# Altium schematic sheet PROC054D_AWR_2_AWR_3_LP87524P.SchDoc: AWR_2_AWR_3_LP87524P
size 558 x 431 mm; Date: Not shown in title block; ApprovedBy: Not shown in title block; CheckedBy: Not shown in title block; Author: Not shown in title block; CompanyName: Not shown in title block; DrawnBy: a0271760; Engineer: Not shown in title block; Organization: Not shown in title block; Address1: Not shown in title block; Address2: Not shown in title block; Address3: Not shown in title block; Address4: Not shown in title block; DocumentNumber: 5; Revision: Use project pAWRameter SCH_Rev; SheetNumber: 5; SheetTotal: 19; PageSetup: Record=PageOptions¦CenterHorizontal=True¦CenterVertical=True¦PrintScale=1.00¦XCorrection=1.00¦YCorrection=1.00¦PrintKind=0¦BorderSize=5000000¦LeftOffset=0¦BottomOffset=0¦Orientation=2¦PaperLength=1000¦PaperWidth=1000¦Scale=100¦PaperSource=15¦PrintQuality=600¦MediaType=1¦DitherType=10¦PaperKind=Letter¦PrintScaleMode=1
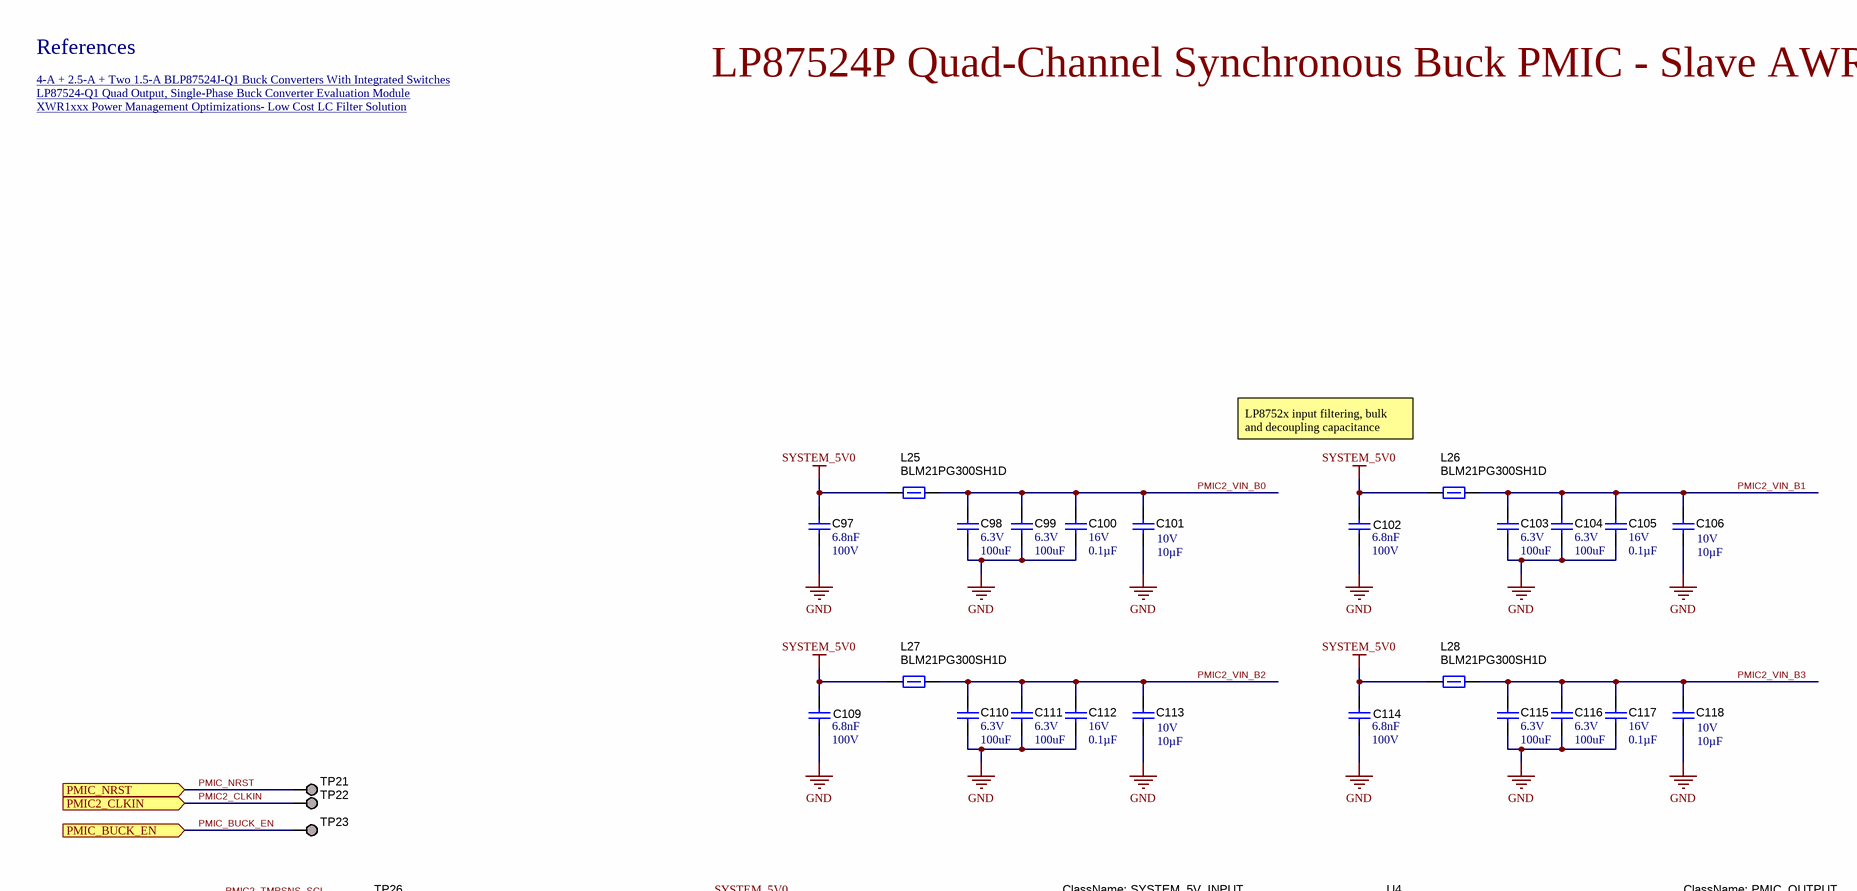
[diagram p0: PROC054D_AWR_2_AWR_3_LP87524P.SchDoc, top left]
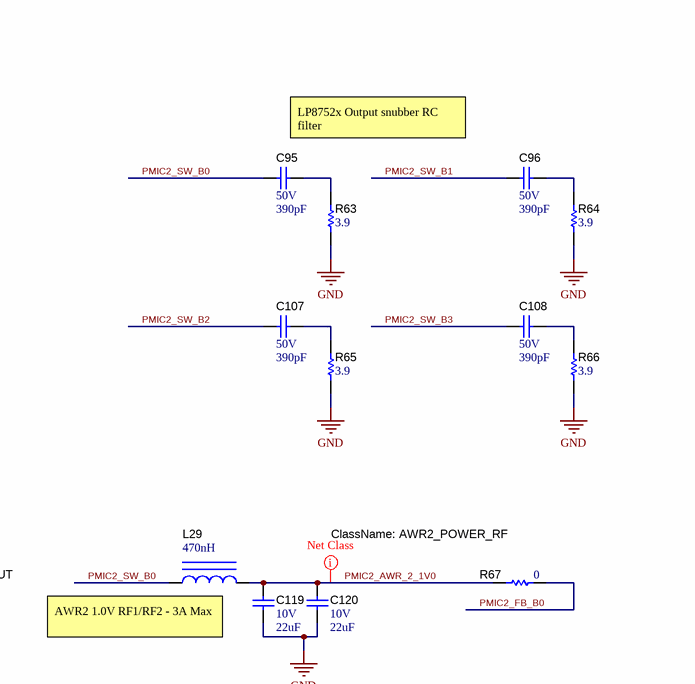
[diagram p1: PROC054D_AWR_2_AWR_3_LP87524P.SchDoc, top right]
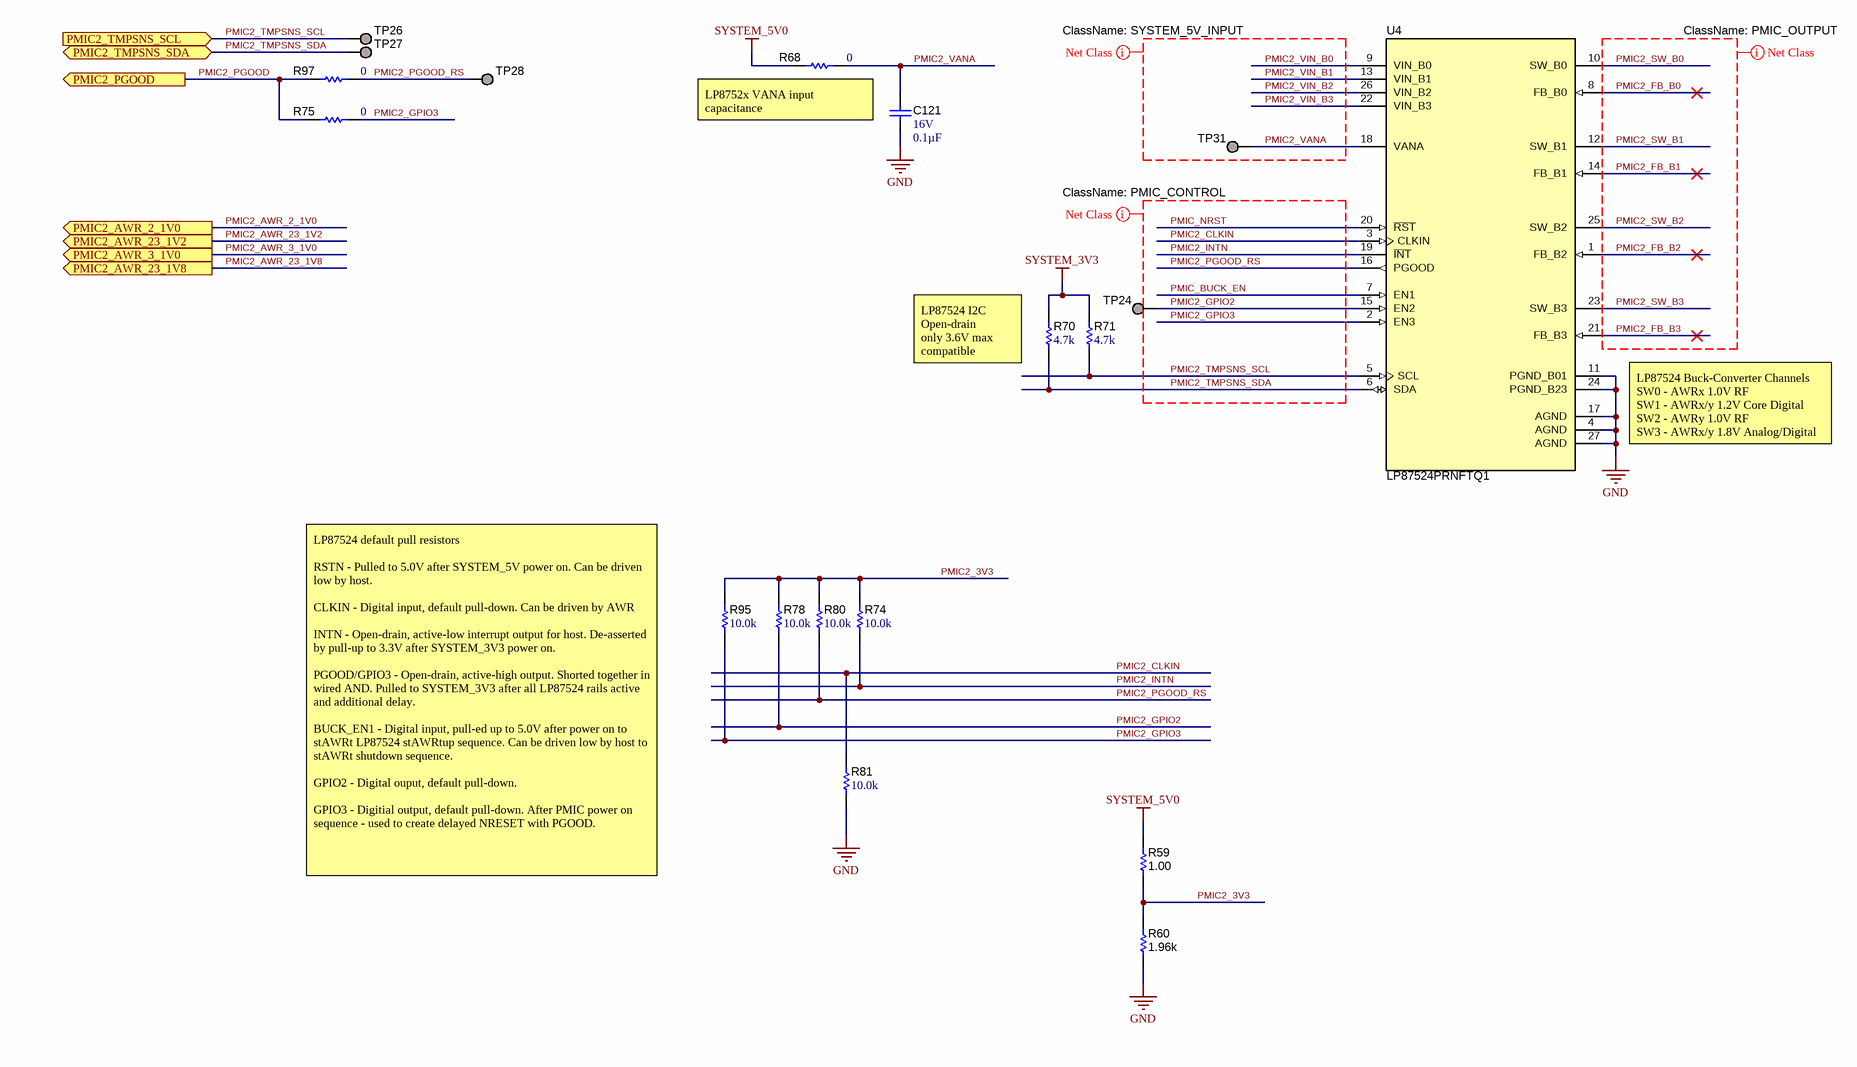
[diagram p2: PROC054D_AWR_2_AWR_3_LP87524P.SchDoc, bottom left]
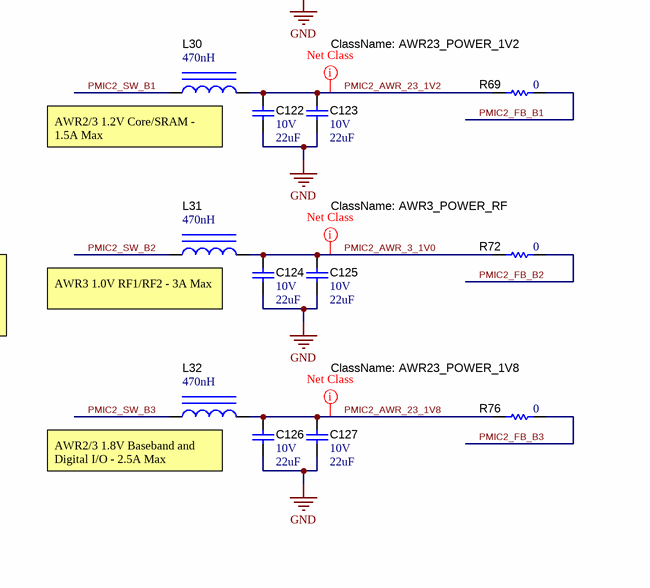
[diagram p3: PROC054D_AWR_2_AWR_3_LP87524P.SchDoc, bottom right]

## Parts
C95  VDC_V: 50V  ValueDisplayed: 390pF  [0402S]  (hidden comment: GCM155R71H391KA37D)
C96  VDC_V: 50V  ValueDisplayed: 390pF  [0402S]  (hidden comment: GCM155R71H391KA37D)
C97  Cap_F: 6.8nF  VDC_V: 100V  [0603S]  (hidden comment: GCM188R72A682KA37D)
C98  VDC_V: 6.3V  ValueDisplayed: 100uF  [0805L]  (hidden comment: GRM21BR60J107M)
C99  VDC_V: 6.3V  ValueDisplayed: 100uF  [0805L]  (hidden comment: GRM21BR60J107M)
C100  VDC_V: 16V  ValueDisplayed: 0.1µF  [0402S]  (hidden comment: GCM155R71C104JA55D)
C101  Cap_F: 10µF  VDC_V: 10V  [0805L]  (hidden comment: GRM21BR71A106KA73L)
C102  Cap_F: 6.8nF  VDC_V: 100V  [0603S]  (hidden comment: GCM188R72A682KA37D)
C103  VDC_V: 6.3V  ValueDisplayed: 100uF  [0805L]  (hidden comment: GRM21BR60J107M)
C104  VDC_V: 6.3V  ValueDisplayed: 100uF  [0805L]  (hidden comment: GRM21BR60J107M)
C105  VDC_V: 16V  ValueDisplayed: 0.1µF  [0402S]  (hidden comment: GCM155R71C104JA55D)
C106  Cap_F: 10µF  VDC_V: 10V  [0805L]  (hidden comment: GRM21BR71A106KA73L)
C107  VDC_V: 50V  ValueDisplayed: 390pF  [0402S]  (hidden comment: GCM155R71H391KA37D)
C108  VDC_V: 50V  ValueDisplayed: 390pF  [0402S]  (hidden comment: GCM155R71H391KA37D)
C109  Cap_F: 6.8nF  VDC_V: 100V  [0603S]  (hidden comment: GCM188R72A682KA37D)
C110  VDC_V: 6.3V  ValueDisplayed: 100uF  [0805L]  (hidden comment: GRM21BR60J107M)
C111  VDC_V: 6.3V  ValueDisplayed: 100uF  [0805L]  (hidden comment: GRM21BR60J107M)
C112  VDC_V: 16V  ValueDisplayed: 0.1µF  [0402S]  (hidden comment: GCM155R71C104JA55D)
C113  Cap_F: 10µF  VDC_V: 10V  [0805L]  (hidden comment: GRM21BR71A106KA73L)
C114  Cap_F: 6.8nF  VDC_V: 100V  [0603S]  (hidden comment: GCM188R72A682KA37D)
C115  VDC_V: 6.3V  ValueDisplayed: 100uF  [0805L]  (hidden comment: GRM21BR60J107M)
C116  VDC_V: 6.3V  ValueDisplayed: 100uF  [0805L]  (hidden comment: GRM21BR60J107M)
C117  VDC_V: 16V  ValueDisplayed: 0.1µF  [0402S]  (hidden comment: GCM155R71C104JA55D)
C118  Cap_F: 10µF  VDC_V: 10V  [0805L]  (hidden comment: GRM21BR71A106KA73L)
C119  VDC_V: 10V  ValueDisplayed: 22uF  [0805L]  (hidden comment: C2012X7S1A226M125AC)
C120  VDC_V: 10V  ValueDisplayed: 22uF  [0805L]  (hidden comment: C2012X7S1A226M125AC)
C121  VDC_V: 16V  ValueDisplayed: 0.1µF  [0402S]  (hidden comment: GCM155R71C104JA55D)
C122  VDC_V: 10V  ValueDisplayed: 22uF  [0805L]  (hidden comment: C2012X7S1A226M125AC)
C123  VDC_V: 10V  ValueDisplayed: 22uF  [0805L]  (hidden comment: C2012X7S1A226M125AC)
C124  VDC_V: 10V  ValueDisplayed: 22uF  [0805L]  (hidden comment: C2012X7S1A226M125AC)
C125  VDC_V: 10V  ValueDisplayed: 22uF  [0805L]  (hidden comment: C2012X7S1A226M125AC)
C126  VDC_V: 10V  ValueDisplayed: 22uF  [0805L]  (hidden comment: C2012X7S1A226M125AC)
C127  VDC_V: 10V  ValueDisplayed: 22uF  [0805L]  (hidden comment: C2012X7S1A226M125AC)
L25  BLM21PG300SH1D  [0805_HV]
L26  BLM21PG300SH1D  [0805_HV]
L27  BLM21PG300SH1D  [0805_HV]
L28  BLM21PG300SH1D  [0805_HV]
L29  ValueDisplayed: 470nH  [DFE252012P]  (hidden comment: DFE252012PD-R47M)
L30  ValueDisplayed: 470nH  [DFE252012P]  (hidden comment: DFE252012PD-R47M)
L31  ValueDisplayed: 470nH  [DFE252012P]  (hidden comment: DFE252012PD-R47M)
L32  ValueDisplayed: 470nH  [DFE252012P]  (hidden comment: DFE252012PD-R47M)
R59  ValueDisplayed: 1.00  [0603]  (hidden comment: CRCW06031R00FKEA)
R60  ValueDisplayed: 1.96k  [0603]  (hidden comment: CRCW06031K96FKEA)
R63  ValueDisplayed: 3.9  [0402S]  (hidden comment: CRCW04023R90JNED)
R64  ValueDisplayed: 3.9  [0402S]  (hidden comment: CRCW04023R90JNED)
R65  ValueDisplayed: 3.9  [0402S]  (hidden comment: CRCW04023R90JNED)
R66  ValueDisplayed: 3.9  [0402S]  (hidden comment: CRCW04023R90JNED)
R67  ValueDisplayed: 0  [0402S]  (hidden comment: CRCW04020000Z0ED)
R68  ValueDisplayed: 0  [0603S]  (hidden comment: MCT06030Z0000ZP500)
R69  ValueDisplayed: 0  [0402S]  (hidden comment: CRCW04020000Z0ED)
R70  ValueDisplayed: 4.7k  [0402]  (hidden comment: CRCW04024K70JNED)
R71  ValueDisplayed: 4.7k  [0402]  (hidden comment: CRCW04024K70JNED)
R72  ValueDisplayed: 0  [0402S]  (hidden comment: CRCW04020000Z0ED)
R74  ValueDisplayed: 10.0k  [0402]  (hidden comment: CRCW040210K0FKED)
R75  ValueDisplayed: 0  [0603]  (hidden comment: MCT06030Z0000ZP500)
R76  ValueDisplayed: 0  [0402S]  (hidden comment: CRCW04020000Z0ED)
R78  ValueDisplayed: 10.0k  [0402S]  (hidden comment: CRCW040210K0FKED)
R80  ValueDisplayed: 10.0k  [0402]  (hidden comment: CRCW040210K0FKED)
R81  ValueDisplayed: 10.0k  [0402]  (hidden comment: CRCW040210K0FKED)
R95  ValueDisplayed: 10.0k  [0402]  (hidden comment: CRCW040210K0FKED)
R97  ValueDisplayed: 0  [0603]  (hidden comment: MCT06030Z0000ZP500)
TP21  TP_SM_1MM  [TP_SM_1MM]  (value not drawn)  (no BOM)
TP22  TP_SM_1MM  [TP_SM_1MM]  (value not drawn)  (no BOM)
TP23  TP_SM_1MM  [TP_SM_1MM]  (value not drawn)  (no BOM)
TP24  TP_SM_1MM  [TP_SM_1MM]  (value not drawn)  (no BOM)
TP26  TP_SM_1MM  [TP_SM_1MM]  (value not drawn)  (no BOM)
TP27  TP_SM_1MM  [TP_SM_1MM]  (value not drawn)  (no BOM)
TP28  TP_SM_1MM  [TP_SM_1MM]  (value not drawn)  (no BOM)
TP31  TP_SM_1MM  [TP_SM_1MM]  (value not drawn)  (no BOM)
U4  LP87524PRNFTQ1  [RNF0026C]

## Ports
PMIC2_AWR_2_1V0 (out), PMIC2_AWR_3_1V0 (out), PMIC2_AWR_23_1V2 (out), PMIC2_AWR_23_1V8 (out), PMIC2_CLKIN (in), PMIC2_PGOOD (out), PMIC2_TMPSNS_SCL (in), PMIC2_TMPSNS_SDA (bidir), PMIC_BUCK_EN (in), PMIC_NRST (in)

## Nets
GND: C97.2 C98.2 C99.2 C100.2 C101.2 C102.2 C103.2 C104.2 C105.2 C106.2 C109.2 C110.2 C111.2 C112.2 C113.2 C114.2 C115.2 C116.2 C117.2 C118.2 C119.2 C120.2 C121.2 C122.2 C123.2 C124.2 C125.2 C126.2 C127.2 R60.1 R63.1 R64.1 R65.1 R66.1 R81.1 U4.4(AGND) U4.11(PGND_B01) U4.17(AGND) U4.24(PGND_B23) U4.27(AGND)
SYSTEM_3V3: R70.1 R71.2
SYSTEM_5V0: C97.1 C102.1 C109.1 C114.1 L25.1 L26.1 L27.1 L28.1 R59.2 R68.1
PMIC2_3V3: R59.1 R60.2 R74.2 R78.2 R80.2 R95.2
PMIC2_AWR_2_1V0: C119.1 C120.1 L29.2 R67.1 ; port PMIC2_AWR_2_1V0
PMIC2_AWR_3_1V0: C124.1 C125.1 L31.2 R72.1 ; port PMIC2_AWR_3_1V0
PMIC2_AWR_23_1V2: C122.1 C123.1 L30.2 R69.1 ; port PMIC2_AWR_23_1V2
PMIC2_AWR_23_1V8: C126.1 C127.1 L32.2 R76.1 ; port PMIC2_AWR_23_1V8
PMIC2_CLKIN: R81.2 TP22.1 U4.3(CLKIN) ; port PMIC2_CLKIN
PMIC2_FB_B0: R67.2 U4.8(FB_B0)
PMIC2_FB_B1: R69.2 U4.14(FB_B1)
PMIC2_FB_B2: R72.2 U4.1(FB_B2)
PMIC2_FB_B3: R76.2 U4.21(FB_B3)
PMIC2_GPIO2: R78.1 TP24.1 U4.15(EN2)
PMIC2_GPIO3: R75.2 R95.1 U4.2(EN3)
PMIC2_INTN: R74.1 U4.19(~{INT})
PMIC2_PGOOD: R75.1 R97.1 ; port PMIC2_PGOOD
PMIC2_PGOOD_RS: R80.1 R97.2 TP28.1 U4.16(PGOOD)
PMIC2_SW_B0: C95.1 L29.1 U4.10(SW_B0)
PMIC2_SW_B1: C96.1 L30.1 U4.12(SW_B1)
PMIC2_SW_B2: C107.1 L31.1 U4.25(SW_B2)
PMIC2_SW_B3: C108.1 L32.1 U4.23(SW_B3)
PMIC2_TMPSNS_SCL: R71.1 TP26.1 U4.5(SCL) ; port PMIC2_TMPSNS_SCL
PMIC2_TMPSNS_SDA: R70.2 TP27.1 U4.6(SDA) ; port PMIC2_TMPSNS_SDA
PMIC2_VANA: C121.1 R68.2 TP31.1 U4.18(VANA)
PMIC2_VIN_B0: C98.1 C99.1 C100.1 C101.1 L25.2 U4.9(VIN_B0)
PMIC2_VIN_B1: C103.1 C104.1 C105.1 C106.1 L26.2 U4.13(VIN_B1)
PMIC2_VIN_B2: C110.1 C111.1 C112.1 C113.1 L27.2 U4.26(VIN_B2)
PMIC2_VIN_B3: C115.1 C116.1 C117.1 C118.1 L28.2 U4.22(VIN_B3)
PMIC_BUCK_EN: TP23.1 U4.7(EN1) ; port PMIC_BUCK_EN
PMIC_NRST: TP21.1 U4.20(~{RST}) ; port PMIC_NRST
NetC95_2: C95.2 R63.2
NetC96_2: C96.2 R64.2
NetC107_2: C107.2 R65.2
NetC108_2: C108.2 R66.2

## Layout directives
net class SYSTEM_5V_INPUT: PMIC2_VANA, PMIC2_VIN_B0, PMIC2_VIN_B1, PMIC2_VIN_B2, PMIC2_VIN_B3
net class PMIC_CONTROL: PMIC2_CLKIN, PMIC2_GPIO2, PMIC2_GPIO3, PMIC2_INTN, PMIC2_PGOOD_RS, PMIC2_TMPSNS_SCL, PMIC2_TMPSNS_SDA, PMIC_BUCK_EN, PMIC_NRST
net class PMIC_OUTPUT: PMIC2_FB_B0, PMIC2_FB_B1, PMIC2_FB_B2, PMIC2_FB_B3, PMIC2_SW_B0, PMIC2_SW_B1, PMIC2_SW_B2, PMIC2_SW_B3
net class AWR23_POWER_1V2: PMIC2_AWR_23_1V2
net class AWR23_POWER_1V8: PMIC2_AWR_23_1V8
net class AWR2_POWER_RF: PMIC2_AWR_2_1V0
net class AWR3_POWER_RF: PMIC2_AWR_3_1V0

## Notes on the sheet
- References
- LP87524-Q1 Quad Output, Single-Phase Buck Converter Evaluation Module <http://www.ti.com/tool/lp87524q1evm>
- 4-A + 2.5-A + Two 1.5-A BLP87524J-Q1 Buck Converters With Integrated Switches <http://www.ti.com/product/lp87524j-q1>
- XWR1xxx Power Management Optimizations- Low Cost LC Filter Solution <http://www.ti.com/lit/pdf/swra577>
- LP87524P Quad-Channel Synchronous Buck PMIC - Slave AWR_2 and Slave AWR_3
- LP8752x input filtering, bulk and decoupling capacitance
- (near C95) LP8752x Output snubber RC filter
- (near L29) AWR2 1.0V RF1/RF2 - 3A Max
- (near R68) LP8752x VANA input capacitance
- (near L30) AWR2/3 1.2V Core/SRAM - 1.5A Max
- (near R70) LP87524 I2C
  Open-drain
  only 3.6V max compatible
- (near L31) AWR3 1.0V RF1/RF2 - 3A Max
- LP87524 Buck-Converter Channels
  SW0 - AWRx 1.0V RF
  SW1 - AWRx/y 1.2V Core Digital
  SW2 - AWRy 1.0V RF
  SW3 - AWRx/y 1.8V Analog/Digital
- (near L32) AWR2/3 1.8V Baseband and Digital I/O - 2.5A Max
- LP87524 default pull resistors
  RSTN - Pulled to 5.0V after SYSTEM_5V power on. Can be driven low by host.
  CLKIN - Digital input, default pull-down. Can be driven by AWR
  INTN - Open-drain, active-low interrupt output for host. De-asserted by pull-up to 3.3V after SYSTEM_3V3 power on.
  PGOOD/GPIO3 - Open-drain, active-high output. Shorted together in wired AND. Pulled to SYSTEM_3V3 after all LP87524 rails active and additional delay.
  BUCK_EN1 - Digital input, pull-ed up to 5.0V after power on to stAWRt LP87524 stAWRtup sequence. Can be driven low by host to stAWRt shutdown sequence.
  GPIO2 - Digital ouput, default pull-down.
  GPIO3 - Digitial output, default pull-down. After PMIC power on sequence - used to create delayed NRESET with PGOOD.

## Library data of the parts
C95 C96 C107 C108 = CMP-0080703-2: CAP, CERM, 390 pF, 50 V,+/- 10%, X7R, AEC-Q200 Grade 1, 0402; Manufacturer: MuRata; Cap_Case: 0402; SizeX_mm: 1; SizeZ_mm: 0.6; SizeY_mm: 0.5; AEC Qualified: Y; Value: 390pF; Polarized: N; AEC Category: Q200; TaMax_C: 125°C; TaMin_C: -55°C; SizeAreaWB_mm2: 3; U/M: EA
C97 C102 C109 C114 = CMP-0860888-1: CAP, CERM, 6800 pF, 100 V,+/- 10%, X7R, AEC-Q200 Grade 1, 0603; Manufacturer: MuRata; AEC Grade: 1; AEC Qualified: Y; TaMin_C: -55°C; AEC Category: Q200; SizeY_mm: 0.8; Cap_Case: 0603; ValueDisplayed: 6800pF; Polarized: N; SizeArea_mm2: 1.28; U/M: EA; SizeX_mm: 1.6; SizeAreaWB_mm2: 4.68; TaMax_C: 125°C; Value: 6800pF
C98 C99 C103 C104 C110 C111 C115 C116 = CMP-0008280-2: CAP, CERM, 100 uF, 6.3 V, +/- 20%, X5R, 0805; Manufacturer: MuRata; TaMin_C: -55°C; Polarized: N; SizeAreaWB_mm2: 6.75; Value1: Unknown; U/M: EA; Value: 100uF; TaMax_C: 85°C; SizeZ_mm: 1.45; SizeX_mm: 2; SizeY_mm: 1.25; Cap_Case: 0805; SizeArea_mm2: 2.5; Cap_F: 100µF; AEC Category: Q200
C100 C105 C112 C117 C121 = CMP-0080702-1: CAP, CERM, 0.1 µF, 16 V,+/- 5%, X7R, AEC-Q200 Grade 1, 0402; Manufacturer: MuRata; Cap_F: 100nF; SizeAreaWB_mm2: 3; SizeArea_mm2: 0.5; AEC Qualified: Y; AEC Category: Q200; Value: 0.1uF; TaMax_C: 125°C; SizeZ_mm: 0.6; AEC Grade: 1; Polarized: N; TaMin_C: -55°C; U/M: EA; Cap_Case: 0402
C101 C106 C113 C118 = CMP-0081849-1: CAP, CERM, 10 µF,  V,+/- 10%, X7R, 0805; Manufacturer: MuRata; TaMin_C: -55°C; Polarized: N; Green_Lifecycle: Active; SizeAreaWB_mm2: 6.75; Green_REACh: Passed; U/M: EA; Value: 10uF; TaMax_C: 125°C; SizeZ_mm: 1.45; SizeX_mm: 2; SizeY_mm: 1.25; Cap_Case: 0805; SizeArea_mm2: 2.5; AEC Category: Q200
C119 C120 C122-C127 = CMP-0007890-1: CAP, CERM, 22 uF, 10 V, +/- 20%, X7S, 0805; Manufacturer: TDK; TaMin_C: -55°C; ESR_ohm: 2.05m; Polarized: N; SizeAreaWB_mm2: 6.75; Value1: 0.00205 ohm; U/M: EA; Value: 22uF; TaMax_C: 125°C; SizeZ_mm: 1.45; SizeX_mm: 2; SizeY_mm: 1.25; Cap_Case: 0805; SizeArea_mm2: 2.5; Cap_F: 22µF; IRMS_A: 4.5559A; AEC Category: Q200
L25-L28 = CMP-0003364-1: Ferrite Bead, 30 ohm @ 100 MHz, 4 A, 0805; Manufacturer: MuRata; ZTyp@100MHz_Ohm: 30; SizeAreaWB_mm2: 6.75; DCR_ohm: 0.014; Value1: 0.014 ohm; Value: 30 ohm; Imax_A: 4A; SizeZ_mm: 1.45; SizeX_mm: 2; SizeY_mm: 1.25; SizeArea_mm2: 2.5
L29-L32 = CMP-0058944-1: Inductor, Shielded, 470 nH, 4.7 A, 0.021 ohm, SMD; Manufacturer: MuRata Toko; Isat: 6.1A @ 30% inductance drop; Irms: 4.7A @ 40C rise; SizeAreaWB_mm2: 10.5; DCR_ohm: 0.021; Value: 470nH; Imax_A: 4.7A; SizeZ_mm: 1.2; SizeX_mm: 2.5; SizeY_mm: 2; SizeArea_mm2: 5; AEC Category: Q200
R59 = CMP-0022170-4: RES, 1.00, 1%, 0.1 W, AEC-Q200 Grade 0, 0603; Manufacturer: Vishay-Dale; Power_W: 100mW; TempCo: 100 ppm/C; Value_Code: 1R00; Value: 1.00; EIA_Code: E96; Res_ohm: 1; SizeX_mm: 1.6; SizeY_mm: 0.8; Value2: 0.1W; SizeArea_mm2: 1.28; AEC Qualified: Y; VDC_V: 75V; AEC Category: Q200; AEC Grade: 0
R60 = CMP-0022137-4: RES, 1.96 k, 1%, 0.1 W, AEC-Q200 Grade 0, 0603; Manufacturer: Vishay-Dale; Power_W: 100mW; TempCo: 100 ppm/C; Value_Code: 1k96; Value: 1.96k; EIA_Code: E96; SizeX_mm: 1.6; SizeY_mm: 0.8; SizeZ_mm: 1; Value2: 0.1W; SizeArea_mm2: 1.28; AEC Qualified: Y; VDC_V: 75V; AEC Category: Q200; AEC Grade: 0
R63-R66 = CMP-0026928-3: RES, 3.9, 5%, 0.063 W, AEC-Q200 Grade 0, 0402; Manufacturer: Vishay-Dale; Power_W: 63mW; TempCo: 200 ppm/C; Value_Code: 3R90; Value: 3.9; EIA_Code: E24; SizeX_mm: 1; SizeY_mm: 0.5; SizeZ_mm: 0.6; Value2: 0.063W; AEC Qualified: Y; VDC_V: 50V; AEC Category: Q200; AEC Grade: 0
R67 R69 R72 R76 = CMP-0026822-3: RES, 0, 5%, 0.063 W, AEC-Q200 Grade 0, 0402; Manufacturer: Vishay-Dale; Power_W: 63mW; TempCo: 200 ppm/C; Value_Code: 0000; Value: 0; EIA_Code: E24; SizeX_mm: 1; SizeY_mm: 0.5; SizeZ_mm: 0.6; Value2: 0.063W; AEC Qualified: Y; VDC_V: 50V; AEC Category: Q200
R68 R75 R97 = CMP-0025884-3: RES, 0, 5%, 0.125 W, 0603; Manufacturer: Vishay/Beyschlag; Power_W: 125mW; TempCo: ppm/C; Value_Code: 0000; U/M: EA; Value: 0; EIA_Code: E24; SizeX_mm: 1.6; SizeY_mm: 0.8; SizeZ_mm: 1; Value2: 0.125W; SizeArea_mm2: 1.28; AEC Qualified: N; AEC Category: Q200
R70 R71 = CMP-0026938-5: RES, 4.7 k, 5%, 0.063 W, AEC-Q200 Grade 0, 0402; Manufacturer: Vishay-Dale; Power_W: 63mW; TempCo: 200 ppm/C; Value_Code: 4k70; Value: 4.7k; EIA_Code: E24; SizeX_mm: 1; SizeY_mm: 0.5; SizeZ_mm: 0.6; Value2: 0.063W; AEC Qualified: Y; VDC_V: 50V; AEC Category: Q200; AEC Grade: 0
R74 R78 R80 R81 R95 = CMP-0025958-3: RES, 10.0 k, 1%, 0.063 W, AEC-Q200 Grade 0, 0402; Manufacturer: Vishay-Dale; Power_W: 63mW; TempCo: 100 ppm/C; Value_Code: 10k0; Value: 10.0k; EIA_Code: E96; Res_ohm: 10k; SizeX_mm: 1; SizeY_mm: 0.5; SizeZ_mm: 0.6; Value2: 0.063W; AEC Qualified: Y; VDC_V: 50V; AEC Category: Q200; AEC Grade: 0
TP21-TP24 TP26-TP28 TP31 = CMP-0003825-1: 1mm Test Point, SMT; Manufacturer: Any
U4 = CMP-0083823-1: 4-A + 2.5-A + Two 1.5-A Buck Converters With Integrated Switches, RNF0026C (VQFN-HR-26); Alternate PartNumber: LP87524PRNFRQ1; Alternate Manufacturer: Texas Instruments; SizeAreaWB_mm2: 27.5; Rating: Automotive; SizeZ_mm: 0.9; SizeX_mm: 4; SizeY_mm: 4.5; SizeArea_mm2: 18; CompType: IC; AEC Qualified: Y; AEC Category: Q200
